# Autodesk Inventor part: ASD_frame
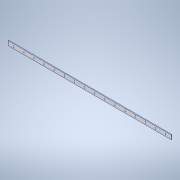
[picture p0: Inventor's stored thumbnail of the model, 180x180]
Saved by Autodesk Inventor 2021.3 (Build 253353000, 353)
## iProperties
Created: 2021-12
Part Number: ASD_frame
Material: アルミニウム 6061
Document SubType Name: Modeling
Designer: kengo
Density: 2.7 g/cm^3
Appearance: アルミニウム - フラット
Author: kengo
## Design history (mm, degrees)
sketch "スケッチ1"
  geometry: L1 (-490.333, 60.646)-(669.667, 60.646); L2 (669.667, 60.646)-(669.667, 30.646); L3 (669.667, 30.646)-(-490.333, 30.646); L4 (-490.333, 30.646)-(-490.333, 60.646); 1 further point
  constraints: 8 end point, 2 parallel, 1 horizontal, 1 perpendicular
  dimensions: "d0" = 1160 distance of L2.end L3.end; "d1" = 30 distance of L3.end L1.start
extrude "押し出し1" new body sketch "スケッチ1" distance "d2" = 5; taper "d3" = 0 deg
sketch "スケッチ2" dims "d11" = 10
  geometry: L1 (-490.333, 30.646)-(669.667, 30.646) reference; L2 (669.667, 30.646)-(669.667, 60.646) reference; L3 (669.667, 60.646)-(-490.333, 60.646) reference; 17 further points
  constraints: 1 horizontal, 15 other
  dimensions: "d4" = 10 distance from line of L1 point (629.667, 40.646); "d6" = 40 distance from line of L2 point (629.667, 40.646); "d8" = 20 distance from line of L3 point (629.667, 40.646) (derived); "d14" = 72 distance of point (629.667, 40.646) point (557.667, 40.646)
hole "穴1" sketch "スケッチ2" at (629.667, 40.646), (557.667, 40.646), (485.667, 40.646), (413.667, 40.646), (341.667, 40.646), (269.667, 40.646), (197.667, 40.646), (125.667, 40.646), (53.667, 40.646), (-18.333, 40.646), (-90.333, 40.646), (-162.333, 40.646)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 diameter "d16" = 4; stored, may be unused: countersink angle "d20" = 90 deg, drill point angle "d22" = 118 deg; dims "d17" = 6, "d18" = 4, "d19" = 2, "d21" = 100
sketch "スケッチ3" dims "d28" = 10
  geometry: L1 (669.667, 60.646)-(-490.333, 60.646) reference; L2 (-490.333, 30.646)-(669.667, 30.646) reference; L3 (669.667, 30.646)-(669.667, 60.646) reference; 17 further points
  constraints: 1 horizontal, 15 other
  dimensions: "d23" = 10 distance from line of L1 point (629.667, 50.646); "d24" = 20 distance from line of L2 point (629.667, 50.646) (derived); "d25" = 40 distance from line of L3 point (629.667, 50.646); "d31" = 72 distance of point (629.667, 50.646) point (557.667, 50.646)
hole "穴2" sketch "スケッチ3" at (629.667, 50.646), (557.667, 50.646), (485.667, 50.646), (413.667, 50.646), (341.667, 50.646), (269.667, 50.646), (197.667, 50.646), (125.667, 50.646), (53.667, 50.646), (-18.333, 50.646), (-90.333, 50.646), (-162.333, 50.646)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 diameter "d33" = 3; stored, may be unused: countersink angle "d37" = 90 deg, drill point angle "d39" = 118 deg; dims "d34" = 6, "d35" = 4, "d36" = 2, "d38" = 100
node "ソリッド1"
